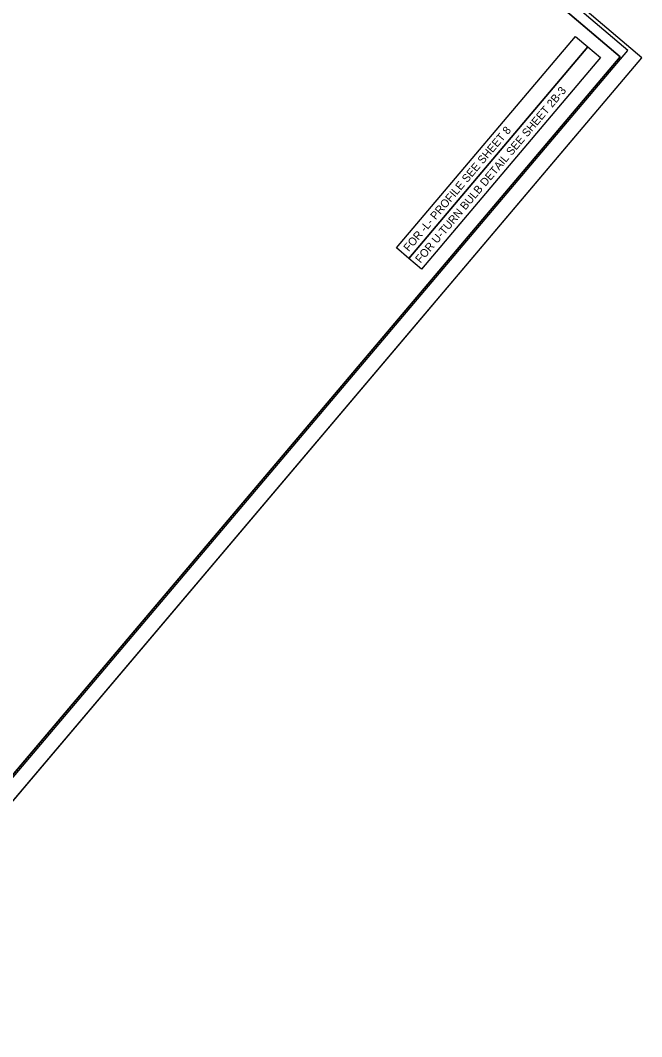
# Model space of a CAD drawing. Extents: x 1761124 to 1764673, y 421930 to 425955.
# Drawn here: x 1763857 to 1764673, y 423854 to 425188 of the extents above; entities that cross this region are included whole.
import ezdxf

# ---------------------------------------------------------------- set-up
doc = ezdxf.new("R2010")
doc.units = 0
for name, color, linetype in [('CTL Primary Horizontal and Vertical Cogo Elevation', 7, 'Continuous'), ('CTL Sheet Datum Description CELL', 7, 'Continuous'), ('Exist Roads Change in Surface', 7, 'Continuous'), ('Exist Roads Change in Surface Text', 7, 'Continuous'), ('Exist Roads EOP Other', 7, 'Continuous'), ('Exist Roads EOP Other Text', 7, 'Continuous'), ('Exist Roads Soil', 7, 'Continuous'), ('Exist Structure Major Deck Tunnel Box Culvert', 7, 'Continuous')]:
    doc.layers.add(name, color=color, linetype=linetype)

msp = doc.modelspace()

# ---------------------------------------------------------------- linework, layer by layer
at = {"layer": 'CTL Sheet Datum Description CELL'}
msp.add_lwpolyline([(1763720.3, 424048.8), (1764644.8, 425140), (1764016.1, 425672.7), (1763886.8, 425520), (1763714.3, 425666.1), (1762919.2, 424727.5)], close=True, dxfattribs=at)
at = {"layer": 'Exist Roads Change in Surface'}
msp.add_lwpolyline([(1763584.8, 423853.9), (1764673, 425138.5), (1763837.5, 425846.3), (1762749.3, 424561.7)], close=True, dxfattribs=at)
at = {"layer": 'Exist Roads Change in Surface Text'}
msp.add_line((1763584.8, 423853.9), (1764673, 425138.5), dxfattribs=at)
at = {"layer": 'Exist Roads EOP Other'}
for points in [[(1763843.7, 425818.8), (1762874, 424674.2), (1763675.2, 423995.5), (1764644.8, 425140)], [(1763675.2, 423995.5), (1762874.1, 424674.2), (1763714.3, 425666.1), (1763828.8, 425569.1), (1763958.1, 425721.7), (1764644.8, 425140)]]:
    msp.add_lwpolyline(points, close=True, dxfattribs=at)
at = {"layer": 'Exist Roads EOP Other Text'}
for points in [[(1764350.7, 424889.1), (1764585.9, 425166.7), (1764602.3, 425152.8), (1764367.1, 424875.2)], [(1764367.1, 424875.2), (1764602.3, 425152.8), (1764618.7, 425138.9), (1764383.5, 424861.3)]]:
    msp.add_lwpolyline(points, close=True, dxfattribs=at)
at = {"layer": 'Exist Roads Soil'}
msp.add_lwpolyline([(1763577.9, 423876.8), (1764654.8, 425148), (1763849.8, 425829.9), (1762772.9, 424558.7)], close=True, dxfattribs=at)
at = {"layer": 'Exist Structure Major Deck Tunnel Box Culvert'}
msp.add_lwpolyline([(1762874.1, 424674.2), (1763675.2, 423995.5), (1764644.8, 425140), (1764005, 425682), (1763850.4, 425499.5), (1763689, 425636.2)], close=True, dxfattribs=at)

# ---------------------------------------------------------------- texts
at = {"layer": 'CTL Primary Horizontal and Vertical Cogo Elevation'}
for s, p in [('FOR U-TURN BULB DETAIL SEE SHEET 2B-3', (1764382.4, 424868.4)), ('FOR -L- PROFILE SEE SHEET 8', (1764367, 424883.5))]:
    msp.add_text(s, height=10.5, rotation=49.7301, dxfattribs=at).set_placement(p)

doc.saveas('drawing.dxf')
